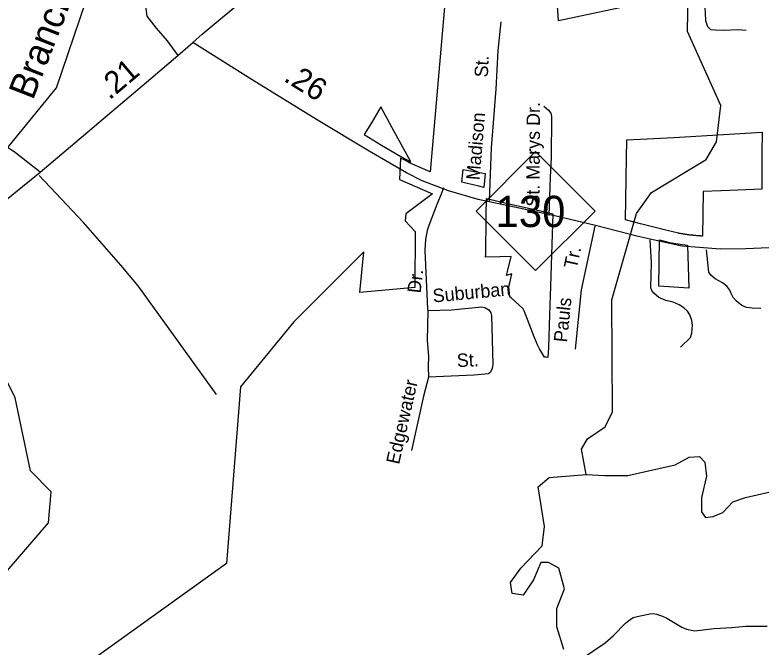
# Model space of a CAD drawing. Extents: x 2104537 to 2336408, y 34176 to 229611.
# Drawn here: x 2188998 to 2193201, y 81491 to 85032 of the extents above; entities that cross this region are included whole.
import ezdxf

# ---------------------------------------------------------------- set-up
doc = ezdxf.new("R2010")
doc.units = 0
for name, color, linetype in [('Exist Boundary Political City Limit New', 7, 'Continuous'), ('Exist Boundary Political City Limit New Hole', 7, 'Continuous'), ('Exist Hydrographic Creek Single Shore', 7, 'Continuous'), ('Exist Hydrographic Misc Water Feature', 7, 'Continuous'), ('Exist Road Non-System Type 51', 7, 'Continuous'), ('Exist Road Non-System Type 51 Label', 7, 'Continuous'), ('Exist Road Primary NC Attributed', 7, 'Continuous'), ('Exist Road Primary NC Mileage Hundredths English Label', 7, 'Continuous'), ('Exist Road Primary NC Shield CELL', 7, 'Continuous'), ('Exist Road Primary NC Shield Number Label', 7, 'Continuous'), ('Exist Road Primary US Attributed', 7, 'Continuous'), ('Exist Road Primary US Mileage Hundredths English Label', 7, 'Continuous'), ('Exist Road Secondary Type 51 Attributed', 7, 'Continuous'), ('Map Preparation Boundary City Limit Buffer Line', 7, 'Continuous'), ('Old_Level_32', 7, 'Continuous')]:
    doc.layers.add(name, color=color, linetype=linetype)

msp = doc.modelspace()

# ---------------------------------------------------------------- linework, layer by layer
at = {"layer": 'Exist Boundary Political City Limit New'}
for points in [[(2193106.8, 85227.2), (2192040.2, 84999.4), (2192032.2, 85110.8)], [(2191404.2, 85098.9), (2191321.2, 84155.2), (2191210, 84204), (2191180.2, 84220.9), (2191156.2, 84232.3), (2191149.8, 84112.5), (2191334.5, 84032.9), (2191186, 83920.8), (2191181, 83880.3), (2191236.5, 83822), (2191235, 83507.6), (2190928.5, 83479.1), (2190950, 83707.2), (2190558.2, 83315.2), (2190259, 82951.6), (2190181.5, 81963.7), (2188769.5, 80951)], [(2192849.5, 84045.9), (2192846, 83795.5), (2192841, 83795.8), (2192837, 83796), (2192834, 83796.2), (2192831, 83796.4), (2192827, 83796.7), (2192823, 83797), (2192820, 83797.2), (2192817, 83797.4), (2192813, 83797.8), (2192809, 83798.1), (2192806, 83798.4), (2192803, 83798.7), (2192800.2, 83799), (2192797.2, 83799.3), (2192794.2, 83799.6), (2192791.2, 83799.9), (2192788.2, 83800.2), (2192785.2, 83800.5), (2192782.2, 83800.9), (2192779.2, 83801.2), (2192775.2, 83801.7), (2192771.2, 83802.2), (2192768.2, 83802.6), (2192765.5, 83803), (2192761.5, 83803.5), (2192757.5, 83804), (2192754.5, 83804.5), (2192751.5, 83804.9), (2192748.5, 83805.3), (2192745.5, 83805.8), (2192741.5, 83806.4), (2192738.8, 83806.8), (2192735.8, 83807.3), (2192731.8, 83807.9), (2192728.8, 83808.4), (2192725.8, 83808.9), (2192722.8, 83809.4), (2192720, 83810), (2192717, 83810.5), (2192714, 83811), (2192711, 83811.6), (2192647, 83827), (2192498.5, 83864.1), (2192455, 83875.5), (2192414, 83885.8), (2192416.2, 83998.1), (2192418.5, 84123.7), (2192420.2, 84232), (2192422.5, 84333.8), (2192458, 84335.5), (2192498.5, 84337), (2192685, 84347.4), (2193178.8, 84376.8), (2193178.5, 84262.1), (2193178.2, 84134.6), (2193178.2, 84058.4), (2192999.2, 84051.6), (2192948, 84049.7), (2192849.5, 84045.9)], [(2191626.8, 84125), (2191622.2, 84067.7), (2191594, 84074.1), (2191561.2, 84082.1), (2191528.5, 84089.6), (2191498.8, 84098.2), (2191506, 84167.5), (2191628.5, 84145.9), (2191626.8, 84125)], [(2192003, 83748.5), (2191994.5, 83515.9), (2191989, 83355.5), (2191983, 83172.1), (2191980.8, 83116.8), (2191971.5, 83118), (2191960.8, 83117.4), (2191934.2, 83164.5), (2191922, 83186.8), (2191904, 83231.1), (2191885.2, 83279.6), (2191866.2, 83328.1), (2191847, 83378.3), (2191842.5, 83388.6), (2191773.8, 83450.3), (2191767.8, 83455.2), (2191761, 83512.8), (2191766.5, 83534.7), (2191779, 83584.4), (2191748.5, 83574.7), (2191755.8, 83605.2), (2191773.8, 83682.1), (2191712.2, 83680.4), (2191631.8, 83678.1), (2191632.2, 83695), (2191633.5, 83761.1), (2191634.5, 83832.4), (2191635.5, 83910.6), (2191637.2, 84005.1), (2191685.8, 83993.9), (2191745.8, 83979.6), (2191822, 83963.1), (2191931.8, 83938.5), (2192008.5, 83920.9), (2192003, 83748.5)], [(2192761, 83744.8), (2192768.8, 83503.5), (2192601, 83515.9), (2192605.5, 83774), (2192660.5, 83759.9), (2192719.8, 83749.5), (2192761, 83744.8)]]:
    msp.add_lwpolyline(points, dxfattribs=at)
at = {"layer": 'Exist Boundary Political City Limit New Hole'}
msp.add_lwpolyline([(2191156.8, 84241.4), (2191180.5, 84227), (2191212.8, 84210.3), (2191108.5, 84400.7), (2191045.5, 84518.1), (2190992.2, 84430.2), (2190951.8, 84363.9), (2191049.5, 84303.8), (2191156.8, 84241.4)], dxfattribs=at)
at = {"layer": 'Exist Hydrographic Creek Single Shore'}
for points in [[(2188722.7, 81596.7), (2188721.6, 81672.2), (2188929.6, 81806), (2188953.5, 81923.6), (2189185.7, 82191.5), (2189200.6, 82365), (2189083.5, 82482.1), (2188998.7, 82890.6), (2188922.6, 83046.2), (2188895.5, 83355.2), (2188575.6, 83945.3), (2188591.6, 84010.6), (2188649.5, 84111.3), (2188948.6, 84279.3), (2189229.5, 84625), (2189393.6, 85107.3), (2189390.5, 85658.6), (2189312.6, 86267.1), (2189284.5, 86723.6), (2189250.5, 86865.4), (2189090.5, 87130.9), (2188705.6, 87453.3)], [(2192194.6, 82461.4), (2192298.8, 82455.3), (2192427.1, 82455.3), (2192601.8, 82495.4), (2192693.2, 82516.3), (2192770.1, 82558), (2192829.4, 82562.8), (2192858.3, 82530.7), (2192867.9, 82452.1), (2192839.1, 82333.4), (2192839.1, 82253.2), (2192861.5, 82221.1), (2192904.8, 82226), (2192959.3, 82250), (2193015.4, 82309.4), (2193085.9, 82333.4), (2193217.4, 82362.3)], [(2192069.6, 81481.7), (2192031.1, 81610), (2192031.1, 81712.7), (2192072.8, 81821.7), (2192040.7, 81937.2), (2191983, 81969.3), (2191941.3, 81969.3), (2191899.6, 81873.1), (2191841.9, 81786.4), (2191781, 81796.1), (2191771.4, 81857), (2191829.1, 81937.2), (2191947.7, 82062.3), (2191960.5, 82171.4), (2191925.3, 82392.8), (2191986.7, 82445.7), (2192194.6, 82461.4)]]:
    msp.add_lwpolyline(points, dxfattribs=at)
at = {"layer": 'Exist Hydrographic Misc Water Feature'}
msp.add_lwpolyline([(2192194.6, 82461.4), (2192168.6, 82603), (2192201.6, 82661.4), (2192301.6, 82728.4), (2192342.6, 82812.9), (2192338.5, 83439.6), (2192476.5, 83922.5), (2192559.6, 84039), (2192865.5, 84223.3), (2192923.6, 84323.9), (2192947.5, 84526.9), (2192761.6, 84940.6), (2192767.7, 85258.7), (2192866.6, 85434), (2193131.7, 85625.7), (2193347.6, 85726.5)], dxfattribs=at)
at = {"layer": 'Exist Road Non-System Type 51'}
for p, q in [((2191396.6, 84065), (2191382, 84029.9)), ((2191307.2, 83388.3), (2191307.6, 83380.1))]:
    msp.add_line(p, q, dxfattribs=at)
for points in [[(2192835, 85956.5), (2192839.6, 85858.4), (2192851, 85719.3), (2192853.2, 85580.3), (2192848.7, 85495.9), (2192851, 85287), (2192855.5, 85134.3), (2192860.1, 85043.1), (2192862.4, 85002), (2192873.8, 84967.8), (2192889.7, 84951.9), (2192919.3, 84949.6), (2192969.5, 84947.3), (2193042.4, 84951.9), (2193090.3, 84947.3)], [(2190232.2, 85760.4), (2190177.1, 85709.6), (2190055, 85554.2), (2189873.5, 85349.7), (2189791.3, 85222.7), (2189756, 85158.1), (2189740.5, 85123.9), (2189729.3, 85067.7), (2189735.7, 85025.9), (2189788.5, 84958.3), (2189849.5, 84887.2), (2189908.6, 84806)], [(2191716.7, 84993.5), (2191700.8, 84833.4), (2191689.7, 84617.1), (2191662.1, 84288.6), (2191652.1, 83992.5)], [(2191956.9, 84522.7), (2191983.4, 84500.9), (2191997.5, 84482.9), (2191999.8, 84465.1), (2191998.9, 84234.8), (2191992.2, 84124.7), (2191984.8, 83910.9)], [(2190125.6, 82908.8), (2189687.5, 83517), (2189589.7, 83633.7), (2189380.4, 83872), (2189133.5, 84135.3)], [(2191382, 84029.9), (2191358.1, 83972.6), (2191313.4, 83854), (2191304, 83826), (2191295.2, 83777), (2191291.4, 83715.7), (2191307.2, 83388.3)], [(2192243.8, 83850.2), (2192167.4, 83495), (2192132.8, 83162.7)], [(2192722.9, 83174.3), (2192778.1, 83229), (2192786.1, 83252.8), (2192789.2, 83297), (2192785.1, 83323.3), (2192774.3, 83355), (2192761.2, 83375.3), (2192741.9, 83394.7), (2192715.6, 83410.3), (2192681.5, 83425.7), (2192641.3, 83435.3), (2192601.6, 83452.5), (2192572.9, 83476.4), (2192562.6, 83490.3), (2192556.4, 83506.2), (2192560.8, 83648.2), (2192553, 83774)], [(2193172.2, 83390), (2193124, 83391.6), (2193091, 83396.1), (2193065.9, 83406.8), (2193036.6, 83431), (2193017.9, 83452.3), (2193005.2, 83473.9), (2192998.7, 83493.7), (2192982.1, 83515.4), (2192958.2, 83533.6), (2192915.9, 83556.7), (2192891.4, 83577.2), (2192881.6, 83594.4), (2192867.9, 83718)], [(2191307.6, 83380.1), (2191439.9, 83383.7), (2191609.8, 83399.8), (2191628.1, 83396.5), (2191649.8, 83382.6), (2191660, 83367), (2191664.3, 83350.5), (2191672.2, 83079.4), (2191668.1, 83054.5), (2191659.8, 83034.4), (2191648.5, 83024.4), (2191566.6, 83017.5), (2191312.8, 83006)], [(2191307.6, 83380.1), (2191304, 83211.8), (2191311.2, 83124.1), (2191309.7, 83064.1), (2191312.8, 83006)], [(2191312.8, 83006), (2191284.2, 82899.6), (2191216, 82596.7)], [(2192116, 81394.3), (2192300.5, 81520.7), (2192347.9, 81561.1), (2192415.5, 81630.7), (2192432.8, 81644.4), (2192458.4, 81660.7), (2192480.5, 81667.1), (2192551.3, 81682.8), (2192571.4, 81684.1), (2192588.4, 81680.5), (2192622.6, 81669), (2192646.7, 81657.4), (2192729.4, 81608.2), (2192756.7, 81597.2), (2192803.1, 81587.7), (2192911.6, 81600.4), (2193009.5, 81605.7), (2193087.4, 81613.1), (2193207.5, 81612.4)]]:
    msp.add_lwpolyline(points, dxfattribs=at)
at = {"layer": 'Exist Road Primary NC Attributed'}
msp.add_lwpolyline([(2193216.6, 83729.5), (2193088.2, 83724.5), (2192945, 83722.1), (2192829, 83731.9), (2192730.2, 83739.4), (2192636.4, 83759.1), (2192486.3, 83793.7), (2192246.8, 83855.4), (2192027.1, 83907.3), (2191794.2, 83956.7), (2191589.3, 84001.2), (2191423.9, 84048.1), (2191359.7, 84072.8), (2191275.8, 84104.9), (2191189.4, 84149.4), (2190979.5, 84270.4), (2190685.7, 84448.2), (2190325.2, 84670.5), (2189993.7, 84879.2)], dxfattribs=at)
at = {"layer": 'Exist Road Primary NC Shield CELL'}
msp.add_lwpolyline([(2191578.5, 83935.8), (2191911.5, 84268.8), (2192244.5, 83935.8), (2191911.5, 83602.8)], close=True, dxfattribs=at)
at = {"layer": 'Exist Road Primary US Attributed'}
for points in [[(2189993.7, 84879.2), (2190045.1, 84925.8), (2190311.6, 85149.7), (2190533.8, 85318.3), (2190714, 85446.7), (2190802.9, 85503.5), (2190951.8, 85585.1), (2191050.5, 85634.5), (2191181.4, 85701.1), (2191396.2, 85792.5), (2191623.3, 85891.3), (2192004, 86050.4), (2192317.6, 86183.8), (2192495.3, 86257.9), (2192754.6, 86376.5), (2192787.5, 86392.1), (2192853.3, 86444.8), (2192881.3, 86477.7), (2192904.3, 86525.5), (2192919.2, 86588), (2192927.4, 86644), (2192930.2, 86677.5)], [(2189137.7, 84153.2), (2189757.2, 84677.4), (2189908.6, 84806), (2189993.7, 84879.2)], [(2187181.9, 82537.4), (2187342.1, 82666.5), (2187624.1, 82897.6), (2187975.3, 83191.3), (2188661.6, 83766.9), (2189137.7, 84153.2)]]:
    msp.add_lwpolyline(points, dxfattribs=at)
at = {"layer": 'Exist Road Secondary Type 51 Attributed'}
msp.add_lwpolyline([(2189137.7, 84153.2), (2189001.3, 84261.9), (2188641.8, 84504.5), (2188321.9, 84724.3), (2188035.4, 84920.8), (2187300.5, 85429.4), (2186750.5, 85801.6), (2186612.2, 85897.2)], dxfattribs=at)
at = {"layer": 'Map Preparation Boundary City Limit Buffer Line'}
for points in [[(2193106.8, 85227.2), (2192040.2, 84999.4), (2192032.2, 85110.8)], [(2191404.2, 85098.9), (2191321.2, 84155.2), (2191210, 84204), (2191180.2, 84220.9), (2191156.2, 84232.3), (2191149.8, 84112.5), (2191334.5, 84032.9), (2191186, 83920.8), (2191181, 83880.3), (2191236.5, 83822), (2191235, 83507.6), (2190928.5, 83479.1), (2190950, 83707.2), (2190558.2, 83315.2), (2190259, 82951.6), (2190181.5, 81963.7), (2188769.5, 80951)], [(2191156.8, 84241.4), (2191180.5, 84227), (2191212.8, 84210.3), (2191108.5, 84400.7), (2191045.5, 84518.1), (2190992.2, 84430.2), (2190951.8, 84363.9), (2191049.5, 84303.8), (2191156.8, 84241.4)], [(2192849.5, 84045.9), (2192846, 83795.5), (2192841, 83795.8), (2192837, 83796), (2192834, 83796.2), (2192831, 83796.4), (2192827, 83796.7), (2192823, 83797), (2192820, 83797.2), (2192817, 83797.4), (2192813, 83797.8), (2192809, 83798.1), (2192806, 83798.4), (2192803, 83798.7), (2192800.2, 83799), (2192797.2, 83799.3), (2192794.2, 83799.6), (2192791.2, 83799.9), (2192788.2, 83800.2), (2192785.2, 83800.5), (2192782.2, 83800.9), (2192779.2, 83801.2), (2192775.2, 83801.7), (2192771.2, 83802.2), (2192768.2, 83802.6), (2192765.5, 83803), (2192761.5, 83803.5), (2192757.5, 83804), (2192754.5, 83804.5), (2192751.5, 83804.9), (2192748.5, 83805.3), (2192745.5, 83805.8), (2192741.5, 83806.4), (2192738.8, 83806.8), (2192735.8, 83807.3), (2192731.8, 83807.9), (2192728.8, 83808.4), (2192725.8, 83808.9), (2192722.8, 83809.4), (2192720, 83810), (2192717, 83810.5), (2192714, 83811), (2192711, 83811.6), (2192647, 83827), (2192498.5, 83864.1), (2192455, 83875.5), (2192414, 83885.8), (2192416.2, 83998.1), (2192418.5, 84123.7), (2192420.2, 84232), (2192422.5, 84333.8), (2192458, 84335.5), (2192498.5, 84337), (2192685, 84347.4), (2193178.8, 84376.8), (2193178.5, 84262.1), (2193178.2, 84134.6), (2193178.2, 84058.4), (2192999.2, 84051.6), (2192948, 84049.7), (2192849.5, 84045.9)], [(2191626.8, 84125), (2191622.2, 84067.7), (2191594, 84074.1), (2191561.2, 84082.1), (2191528.5, 84089.6), (2191498.8, 84098.2), (2191506, 84167.5), (2191628.5, 84145.9), (2191626.8, 84125)], [(2192003, 83748.5), (2191994.5, 83515.9), (2191989, 83355.5), (2191983, 83172.1), (2191980.8, 83116.8), (2191971.5, 83118), (2191960.8, 83117.4), (2191934.2, 83164.5), (2191922, 83186.8), (2191904, 83231.1), (2191885.2, 83279.6), (2191866.2, 83328.1), (2191847, 83378.3), (2191842.5, 83388.6), (2191773.8, 83450.3), (2191767.8, 83455.2), (2191761, 83512.8), (2191766.5, 83534.7), (2191779, 83584.4), (2191748.5, 83574.7), (2191755.8, 83605.2), (2191773.8, 83682.1), (2191712.2, 83680.4), (2191631.8, 83678.1), (2191632.2, 83695), (2191633.5, 83761.1), (2191634.5, 83832.4), (2191635.5, 83910.6), (2191637.2, 84005.1), (2191685.8, 83993.9), (2191745.8, 83979.6), (2191822, 83963.1), (2191931.8, 83938.5), (2192008.5, 83920.9), (2192003, 83748.5)], [(2192761, 83744.8), (2192768.8, 83503.5), (2192601, 83515.9), (2192605.5, 83774), (2192660.5, 83759.9), (2192719.8, 83749.5), (2192761, 83744.8)]]:
    msp.add_lwpolyline(points, dxfattribs=at)

# ---------------------------------------------------------------- texts
at = {"layer": 'Exist Road Non-System Type 51 Label'}
for s, rotation, p in [('St.', 87.0706, (2191643.8, 84682.2)), ('St. Marys Dr.', 89.7902, (2191933.9, 83960.3)), ('Madison', 85.1856, (2191597.4, 84106.7)), ('Tr.', 77.8574, (2192141.6, 83609.3)), ('Dr.', 83.3513, (2191267.5, 83473.4)), ('Suburban', 5.4033, (2191339.1, 83423.7)), ('Pauls', 84.0501, (2192087, 83198.7)), ('St.', 2.5939, (2191472, 83062.4)), ('Edgewater', 77.3102, (2191147.1, 82514.7))]:
    msp.add_text(s, height=75, rotation=rotation, dxfattribs=at).set_placement(p)
at = {"layer": 'Exist Road Primary NC Mileage Hundredths English Label'}
msp.add_text('.26', height=125, rotation=328.3372, dxfattribs=at).set_placement((2190495.5, 84666.9))
at = {"layer": 'Exist Road Primary NC Shield Number Label'}
msp.add_text('130', height=175, dxfattribs=at).set_placement((2191687.6, 83846.1))
at = {"layer": 'Exist Road Primary US Mileage Hundredths English Label'}
msp.add_text('.21', height=125, rotation=40.2346, dxfattribs=at).set_placement((2189526.6, 84553.6))
at = {"layer": 'Old_Level_32'}
msp.add_text('Branch', height=150, rotation=68.6694, dxfattribs=at).set_placement((2189097.5, 84551.7))

doc.saveas('drawing.dxf')
